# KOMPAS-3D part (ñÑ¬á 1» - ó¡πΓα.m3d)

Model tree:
1. Эскиз:1
2. Операция выдавливания:1
     Расстояние 1 = 0.6
3. Эскиз:2
4. Вырезать элемент выдавливания:1
     Толщина стенки 1 = 3; Толщина стенки 2 = 3; Расстояние 1 = 10
5. Эскиз:3
6. Вырезать элемент выдавливания:2
     Толщина стенки 1 = 3; Толщина стенки 2 = 3; Расстояние 1 = 10
7. Эскиз:4
8. Вырезать элемент выдавливания:3
     Толщина стенки 1 = 3; Толщина стенки 2 = 3; Расстояние 1 = 10
9. Эскиз:5
10. Вырезать элемент выдавливания:4
     Толщина стенки 1 = 3; Толщина стенки 2 = 3; Расстояние 1 = 10
